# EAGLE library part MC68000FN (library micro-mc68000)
68xxx PROCESSOR
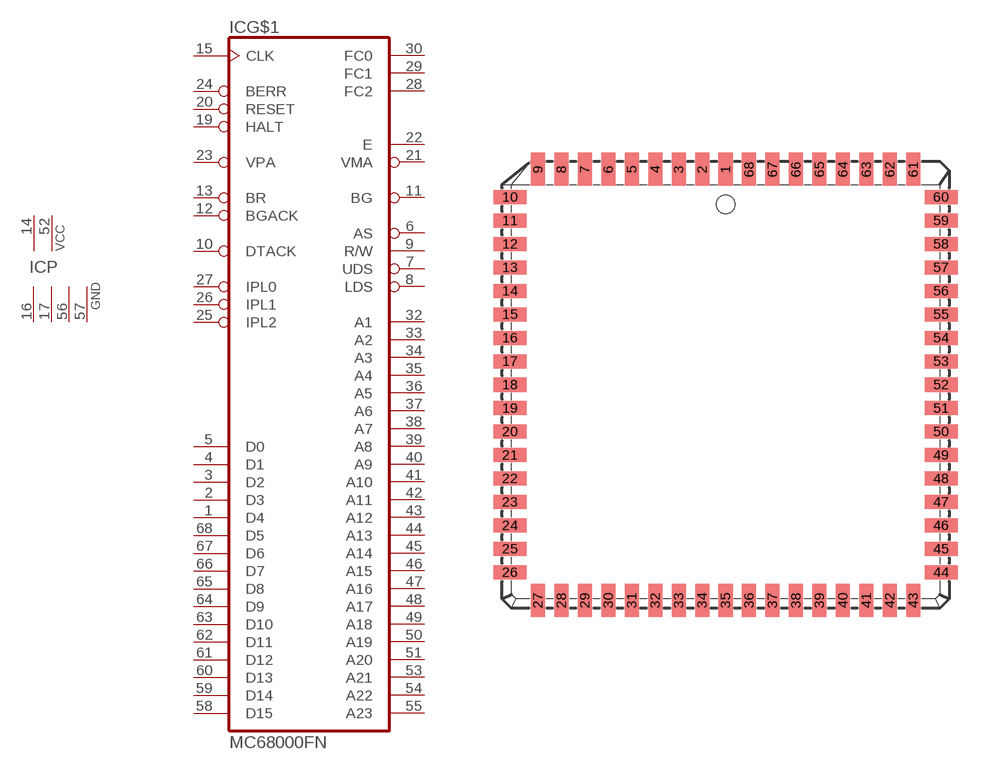
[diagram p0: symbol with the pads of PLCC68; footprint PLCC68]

Designator prefix IC; gates G$1=68000 P=2PWR4GND

## MC68000FN  [PLCC68]
1  G$1:D4
2  G$1:D3
3  G$1:D2
4  G$1:D1
5  G$1:D0
6  G$1:AS  out
7  G$1:UDS  out
8  G$1:LDS  out
9  G$1:R/W  out
10  G$1:DTACK  in
11  G$1:BG  out
12  G$1:BGACK  in
13  G$1:BR  in
14  P:VCC  pwr
15  G$1:CLK  in
16  P:GND  pwr
17  P:GND  pwr
19  G$1:HALT
20  G$1:RESET
21  G$1:VMA  out
22  G$1:E  out
23  G$1:VPA  in
24  G$1:BERR  in
25  G$1:IPL2  in
26  G$1:IPL1  in
27  G$1:IPL0  in
28  G$1:FC2  out
29  G$1:FC1  out
30  G$1:FC0  out
32  G$1:A1  out
33  G$1:A2  out
34  G$1:A3  out
35  G$1:A4  out
36  G$1:A5  out
37  G$1:A6  out
38  G$1:A7  out
39  G$1:A8  out
40  G$1:A9  out
41  G$1:A10  out
42  G$1:A11  out
43  G$1:A12  out
44  G$1:A13  out
45  G$1:A14  out
46  G$1:A15  out
47  G$1:A16  out
48  G$1:A17  out
49  G$1:A18  out
50  G$1:A19  out
51  G$1:A20  out
52  P:VCC  pwr
53  G$1:A21  out
54  G$1:A22  out
55  G$1:A23  out
56  P:GND  pwr
57  P:GND  pwr
58  G$1:D15
59  G$1:D14
60  G$1:D13
61  G$1:D12
62  G$1:D11
63  G$1:D10
64  G$1:D9
65  G$1:D8
66  G$1:D7
67  G$1:D6
68  G$1:D5

## Footprint PLCC68 (pad centres in mm)
PLASTIC LEADED CHIP CARRIER square
smd 0.76 x 1.8: 1 0,11.67; 2 -1.27,11.67; 3 -2.54,11.67; 4 -3.81,11.67; 5 -5.08,11.67; 6 -6.35,11.67; 7 -7.62,11.67; 8 -8.89,11.67; 9 -10.16,11.67; 27 -10.16,-11.67; 28 -8.89,-11.67; 29 -7.62,-11.67; 30 -6.35,-11.67; 31 -5.08,-11.67; 32 -3.81,-11.67; 33 -2.54,-11.67; 34 -1.27,-11.67; 35 0,-11.67; 36 1.27,-11.67; 37 2.54,-11.67; 38 3.81,-11.67; 39 5.08,-11.67; 40 6.35,-11.67; 41 7.62,-11.67; 42 8.89,-11.67; 43 10.16,-11.67; 61 10.16,11.67; 62 8.89,11.67; 63 7.62,11.67; 64 6.35,11.67; 65 5.08,11.67; 66 3.81,11.67; 67 2.54,11.67; 68 1.27,11.67
smd 1.8 x 0.76: 10 -11.67,10.16; 11 -11.67,8.89; 12 -11.67,7.62; 13 -11.67,6.35; 14 -11.67,5.08; 15 -11.67,3.81; 16 -11.67,2.54; 17 -11.67,1.27; 18 -11.67,0; 19 -11.67,-1.27; 20 -11.67,-2.54; 21 -11.67,-3.81; 22 -11.67,-5.08; 23 -11.67,-6.35; 24 -11.67,-7.62; 25 -11.67,-8.89; 26 -11.67,-10.16; 44 11.67,-10.16; 45 11.67,-8.89; 46 11.67,-7.62; 47 11.67,-6.35; 48 11.67,-5.08; 49 11.67,-3.81; 50 11.67,-2.54; 51 11.67,-1.27; 52 11.67,0; 53 11.67,1.27; 54 11.67,2.54; 55 11.67,3.81; 56 11.67,5.08; 57 11.67,6.35; 58 11.67,7.62; 59 11.67,8.89; 60 11.67,10.16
